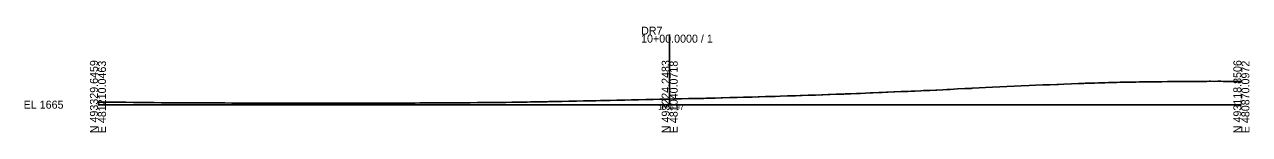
# Model space of a CAD drawing. Extents: x -26 to 403, y -10 to 4215.
# Drawn here: x -25.7 to 402.8, y -9.7 to 27.3 of the extents above; entities that cross this region are included whole.
import ezdxf

# ---------------------------------------------------------------- set-up
doc = ezdxf.new("R2010")
doc.units = 0
for name, color, linetype in [('Exist Cross Section Cell', 7, 'Continuous'), ('Exist XS Center Line Elevation Label', 7, 'Continuous'), ('Exist XS Ground Line', 7, 'Continuous')]:
    doc.layers.add(name, color=color, linetype=linetype)

msp = doc.modelspace()

# ---------------------------------------------------------------- linework, layer by layer
at = {"layer": 'Exist Cross Section Cell'}
for p, q in [((200, 0), (200, 24.53)), ((0, 0), (200, 0)), ((200, 0), (400, 0))]:
    msp.add_line(p, q, dxfattribs=at)
at = {"layer": 'Exist XS Ground Line'}
msp.add_lwpolyline([(0, 0.91), (1.62, 0.89), (2.1, 0.89), (3.69, 0.88), (4.74, 0.86), (7.14, 0.84), (7.75, 0.84), (9.73, 0.82), (12.44, 0.79), (14.6, 0.77), (17.08, 0.75), (17.72, 0.74), (18.79, 0.73), (19.63, 0.72), (22.25, 0.7), (24.4, 0.69), (26.96, 0.68), (29.36, 0.66), (31.95, 0.66), (34.37, 0.65), (36.9, 0.63), (39.37, 0.62), (40.52, 0.61), (41.88, 0.6), (44.39, 0.59), (46.87, 0.58), (49.43, 0.57), (51.91, 0.57), (54.36, 0.56), (56.88, 0.56), (59.39, 0.55), (60.62, 0.55), (63.05, 0.56), (63.96, 0.56), (65.57, 0.55), (68.09, 0.55), (70.6, 0.55), (73.24, 0.55), (75.68, 0.54), (78.02, 0.54), (80.57, 0.54), (83.08, 0.54), (85.62, 0.54), (87.95, 0.54), (88.4, 0.54), (89.8, 0.54), (90.73, 0.54), (93.21, 0.54), (95.56, 0.54), (96.04, 0.54), (98.01, 0.55), (99.94, 0.55), (100.62, 0.55), (102.51, 0.56), (103.5, 0.56), (105.12, 0.56), (105.43, 0.56), (107.87, 0.57), (110.16, 0.58), (110.97, 0.58), (112.59, 0.59), (114.2, 0.59), (115.23, 0.6), (117.76, 0.61), (120.09, 0.62), (120.42, 0.63), (122.86, 0.64), (125.12, 0.66), (127.08, 0.67), (127.69, 0.67), (130.19, 0.69), (132.74, 0.72), (135.05, 0.74), (135.41, 0.74), (137.18, 0.75), (137.84, 0.76), (140.33, 0.79), (142.66, 0.81), (144.74, 0.84), (146.79, 0.87), (147.28, 0.87), (149.57, 0.91), (150.17, 0.92), (151.36, 0.94), (152.4, 0.96), (154.86, 1.01), (157.19, 1.05), (157.74, 1.06), (159.66, 1.09), (161.59, 1.12), (162.25, 1.14), (164.77, 1.19), (165.26, 1.2), (167.38, 1.24), (169.83, 1.29), (171.63, 1.34), (174.14, 1.39), (175.75, 1.43), (176.71, 1.45), (179.22, 1.5), (181.57, 1.55), (181.91, 1.55), (184.31, 1.61), (186.6, 1.67), (188.8, 1.71), (189.15, 1.72), (191.68, 1.78), (194.21, 1.84), (196.53, 1.89), (196.97, 1.9), (198.69, 1.94), (199.31, 1.95), (200, 1.97), (201.56, 2), (203.79, 2.04), (204.13, 2.05), (206.63, 2.11), (208.6, 2.15), (210.88, 2.2), (211.91, 2.22), (212.72, 2.24), (213.46, 2.26), (213.79, 2.27), (215.93, 2.32), (218.02, 2.38), (218.52, 2.39), (221.08, 2.46), (222.75, 2.51), (223.64, 2.53), (225.79, 2.59), (226.72, 2.62), (227.03, 2.62), (228.42, 2.66), (228.9, 2.68), (231, 2.74), (231.31, 2.75), (233.49, 2.81), (234.91, 2.85), (235.95, 2.88), (236.95, 2.91), (238.64, 2.96), (241.18, 3.04), (243.38, 3.11), (243.98, 3.13), (245.6, 3.18), (245.97, 3.19), (246.34, 3.21), (248.44, 3.28), (250.56, 3.35), (251.04, 3.37), (253.27, 3.45), (253.57, 3.46), (255.45, 3.52), (256.14, 3.55), (258.3, 3.63), (259, 3.66), (260.22, 3.7), (260.93, 3.73), (261.34, 3.75), (263.34, 3.83), (265.35, 3.9), (265.99, 3.93), (266.78, 3.96), (268.47, 4.03), (270.15, 4.1), (271.1, 4.13), (273.19, 4.22), (274.3, 4.27), (275.87, 4.33), (276.32, 4.35), (278.46, 4.45), (278.79, 4.47), (280.93, 4.56), (281.93, 4.61), (283.29, 4.67), (284.48, 4.72), (285.5, 4.77), (285.8, 4.78), (287.83, 4.88), (288.82, 4.92), (290.55, 5), (291.04, 5.02), (293.13, 5.12), (293.44, 5.13), (295.6, 5.24), (296.94, 5.3), (297.87, 5.35), (298.17, 5.37), (300.68, 5.5), (303.21, 5.61), (305.53, 5.72), (305.86, 5.74), (308.26, 5.86), (310.45, 5.98), (312.99, 6.12), (315.48, 6.25), (318, 6.37), (320.57, 6.49), (322.98, 6.61), (325.71, 6.72), (327.96, 6.82), (330.51, 6.91), (332.98, 7), (335.42, 7.1), (335.99, 7.12), (337.94, 7.2), (340.58, 7.3), (342.97, 7.4), (344.14, 7.44), (344.94, 7.47), (345.33, 7.48), (346.76, 7.53), (347.65, 7.56), (348.57, 7.59), (350.07, 7.64), (350.58, 7.66), (352.21, 7.7), (353.53, 7.75), (354.02, 7.76), (354.82, 7.78), (355.84, 7.79), (356.46, 7.81), (357.65, 7.84), (359.57, 7.89), (361.29, 7.9), (362.36, 7.93), (363.1, 7.94), (364.31, 7.96), (364.91, 7.96), (365.29, 7.97), (366.74, 7.98), (368.23, 8.02), (368.55, 8.02), (369.06, 8.03), (370.36, 8.02), (371.18, 8.05), (372.18, 8.05), (374.12, 8.07), (375.81, 8.07), (377.06, 8.1), (378.55, 8.11), (379.32, 8.12), (380.5, 8.13), (381.58, 8.14), (383.28, 8.15), (384.48, 8.15), (385.97, 8.16), (386.71, 8.16), (387.97, 8.17), (388.73, 8.18), (389.18, 8.18), (390.64, 8.17), (391.77, 8.18), (392.15, 8.18), (392.78, 8.18), (393.64, 8.17), (394.87, 8.17), (395.8, 8.16), (397.64, 8.16), (398.76, 8.14), (400, 8.12)], dxfattribs=at)

# ---------------------------------------------------------------- texts
at = {"layer": 'Exist Cross Section Cell'}
for s, p in [('DR7', (190, 24.53)), ('10+00.0000 / 1', (190, 21.73)), ('EL 1665', (-26, -1.4))]:
    msp.add_text(s, height=2.8, dxfattribs=at).set_placement(p)
for s, p in [('N 493329.6459', (0, -10)), ('E 481210.0463', (2.8, -10)), ('N 493224.2483', (200, -10)), ('E 481040.0718', (202.8, -10)), ('N 493118.8506', (400, -10)), ('E 480870.0972', (402.8, -10))]:
    msp.add_text(s, height=2.8, rotation=90, dxfattribs=at).set_placement(p)
at = {"layer": 'Exist XS Center Line Elevation Label'}
msp.add_text('1666.97', height=1.8, dxfattribs=at).set_placement((195.95, -1.83))

doc.saveas('drawing.dxf')
